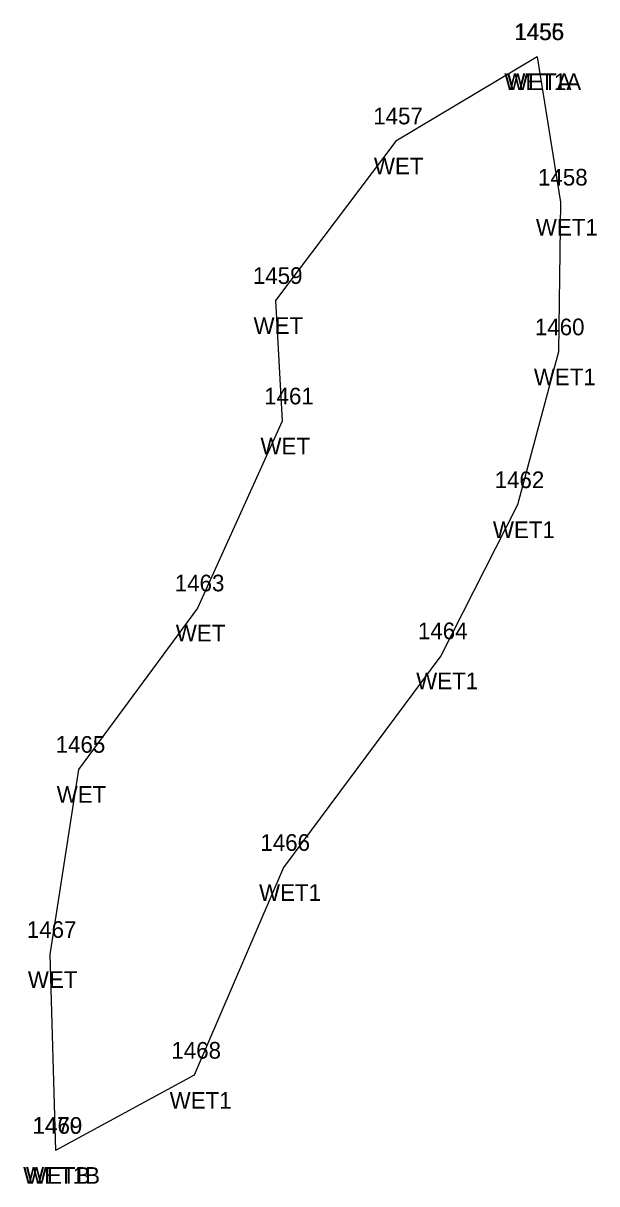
# Model space of a CAD drawing. Extents: x 1967699 to 1968370, y 1117733 to 1117905.
# Drawn here: x 1967698.9 to 1967733.3, y 1117733 to 1117802.6 of the extents above; entities that cross this region are included whole.
import ezdxf

# ---------------------------------------------------------------- set-up
doc = ezdxf.new("R2010")
doc.units = 0
for name, color, linetype in [('RD_EX_H2O_WetLd', 7, 'Continuous'), ('RD_EX_H2O_WetLd_txCode', 7, 'Continuous'), ('RD_SMD_Locator', 7, 'Continuous')]:
    doc.layers.add(name, color=color, linetype=linetype)

msp = doc.modelspace()

# ---------------------------------------------------------------- linework, layer by layer
at = {"layer": 'RD_EX_H2O_WetLd'}
for points in [[(1967729.673, 1117800.597), (1967721.2, 1117795.545), (1967713.987, 1117785.968), (1967714.402, 1117778.742), (1967709.327, 1117767.525), (1967702.187, 1117757.84), (1967700.459, 1117746.735), (1967700.813, 1117734.98)], [(1967729.673, 1117800.597), (1967731.074, 1117791.872), (1967730.951, 1117782.888), (1967728.499, 1117773.718), (1967723.901, 1117764.654), (1967714.481, 1117751.956), (1967709.123, 1117739.488), (1967700.813, 1117734.98)]]:
    msp.add_lwpolyline(points, dxfattribs=at)
at = {"layer": 'RD_SMD_Locator'}
for centre in [(1967729.673, 1117800.597), (1967729.673, 1117800.597), (1967721.2, 1117795.545), (1967731.074, 1117791.872), (1967713.987, 1117785.968), (1967730.951, 1117782.888), (1967714.402, 1117778.742), (1967728.499, 1117773.718), (1967709.327, 1117767.525), (1967723.901, 1117764.654), (1967702.187, 1117757.84), (1967714.481, 1117751.956), (1967700.459, 1117746.735), (1967709.123, 1117739.488), (1967700.813, 1117734.98), (1967700.813, 1117734.98)]:
    msp.add_circle(centre, 0.001, dxfattribs=at)

# ---------------------------------------------------------------- texts
at = {"layer": 'RD_EX_H2O_WetLd_txCode'}
for s, p in [('1456', (1967728.303, 1117801.597)), ('1455', (1967728.327, 1117801.597)), ('WET1A', (1967727.712, 1117798.597)), ('WETA', (1967727.878, 1117798.597)), ('1457', (1967719.853, 1117796.545)), ('WET', (1967719.893, 1117793.545)), ('1458', (1967729.728, 1117792.872)), ('WET1', (1967729.602, 1117789.872)), ('1459', (1967712.64, 1117786.968)), ('WET', (1967712.679, 1117783.968)), ('1460', (1967729.542, 1117783.888)), ('WET1', (1967729.479, 1117780.888)), ('1461', (1967713.316, 1117779.742)), ('WET', (1967713.095, 1117776.742)), ('1462', (1967727.129, 1117774.718)), ('WET1', (1967727.026, 1117771.718)), ('1463', (1967707.956, 1117768.525)), ('WET', (1967708.019, 1117765.525)), ('1464', (1967722.531, 1117765.654)), ('WET1', (1967722.428, 1117762.654)), ('1465', (1967700.817, 1117758.84)), ('WET', (1967700.88, 1117755.84)), ('1466', (1967713.087, 1117752.956)), ('WET1', (1967713.008, 1117749.956)), ('1467', (1967699.089, 1117747.735)), ('WET', (1967699.152, 1117744.735)), ('1468', (1967707.753, 1117740.488)), ('WET1', (1967707.65, 1117737.488)), ('1470', (1967699.427, 1117735.98)), ('1469', (1967699.443, 1117735.98)), ('WET1B', (1967698.868, 1117732.98)), ('WETB', (1967699.034, 1117732.98))]:
    msp.add_text(s, height=1, dxfattribs=at).set_placement(p)

doc.saveas('drawing.dxf')
